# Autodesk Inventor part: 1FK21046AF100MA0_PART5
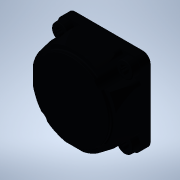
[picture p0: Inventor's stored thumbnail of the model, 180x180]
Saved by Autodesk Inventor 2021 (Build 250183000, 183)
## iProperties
Created: 2025-04
Part Number: 1FK21046AF100MA0_PART5
Material: Generic
Catalog Web Link: www.3dfindit.com
Description: -Servo synchronous motor
Document SubType Name: Modeling
Designer: psAdmin
Mass: 3.92604 g
Surface Area: 17.9521 cm^2
Volume: 3.92604 cm^3
Density: 1 g/cm^3
Appearance: PSOLRGB-48-56-69
Category: PARTsolutions
Title: 1FK21046AF100MA0_PART5
Author: Cadenas PARTsolutions
Comments: Servo synchronous motor
Sending System: PARTsolutions
Preprocessor: ST-DEVELOPER v19.3
PSOL_IDENT_0: {$CADENAS_DATA/23d-libs/siemens_ag/_cat_/4f/2b/1fk21046af100ma0.prj},213 {VTYP=3D},{NB=1FK21046AF100
PSOL_IDENT_1: MA0_PART5},{LINA=1FK21046AF100MA0_PART5},{NN=1FK21046AF100MA0_PART5},{NOPRJ=TRUE},{DATE=19.08.2025 1
PSOL_IDENT_2: 4:00:37},{GEOMDATE=30.07.2025 02:01:06},{VERSION=},{LINEID=10},{WBVAR=},{WBNUMERIC=}  {NB=1FK21046AF
PSOL_IDENT_3: 100MA0_PART5},{LINA=1FK21046AF100MA0_PART5},{KT=DUMMY},{PREVIEW=../../../_pool_/cb/72/p_d211_xx_0043
PSOL_IDENT_4: 4j.png},{DESCSHORT=SIMOTICS S-1FK2 HD, SINAMICS S210 3AC 400V-480V, 3.2 Nm, 3000 rpm},{DESCLONG=SIMO
PSOL_IDENT_5: TICS S-1FK2 HD servo motor M0=3.2 Nm; PN = 1 kW at nN=3000 rpm (380-480 V); PN = 0.5 kW at nN=1500 r
PSOL_IDENT_6: pm (200-240 V); with holding brake; degree of protection IP64; cylindrical shaft D19x40mm; absolute
PSOL_IDENT_7: encoder 22-bit + 12-bit multiturn (encoder AM22DQC); with OCC interface; plug size M17, rotatable; S
PSOL_IDENT_8: IMOTICS S-1FK2 servomotorfor a wide range of uses in industrial environments. SIMOTICS S‑1FK2 servom
PSOL_IDENT_9: otors are compact synchronous motors with a high dynamic performance that set themselves apart as a
PSOL_IDENT_10: result of their high power density, degree of protection and overload capability. The motors are ava
PSOL_IDENT_11: ilable in two variants: as High Dynamic variant (highest dynamic performance as a result of the low
PSOL_IDENT_12: intrinsic moment of inertia for applications demanding a high dynamic performance with low moved mas
PSOL_IDENT_13: ses) - and as Compact variant (precise and stable closed-loop control for medium up to large moved m
PSOL_IDENT_14: asses as a result of a medium intrinsic moment of inertia). SIMOTICSS‑1FK2 servomotors fully exploit
PSOL_IDENT_15: their strengths in a system with the SINAMICSS210 frequency converter and simple connection using t
PSOL_IDENT_16: he one cable connection (OCC). Advantages include the short control and positioning times, fast and
PSOL_IDENT_17: precise correction of disturbing quantities as well as stable control with a high dynamic performanc
PSOL_IDENT_18: e. The servo motors can be configured to address a wide range of requirements. For example with and
PSOL_IDENT_19: without holding brake, IP64 or IP65 degree of protection, singleturn or multiturn absolute encoders
PSOL_IDENT_20: - to name just a few. Further, the servomotors are available in different shaft heights extending fr
PSOL_IDENT_21: om 20 to 100. A shaft sealing ring is available to achieve an IP65 degree of protection and for subs
PSOL_IDENT_22: equent mounting at the motor or as spare part. SIMOTICS - the optimum motor for each and every motio
PSOL_IDENT_23: n control application.},{INTNO=195125049673},{SUPPLIERALTNO=1FK2104-6AF10-0MA0},{MANUID=1FK21046AF10
PSOL_IDENT_24: 0MA0},{MANUNAME=Siemens},{MANUTYPEDESC=Synchronous motor 1FK2-HD 3.2 NM},{AAU732=SIMOTICS},{AAO057=S
PSOL_IDENT_25: -1FK2},{AAU734=SIMOTICS S-1FK2 HD servo motor M0=3.2 Nm; PN = 1 kW at nN=3000 rpm (380-480 V); PN =
PSOL_IDENT_26: 0.5 kW at nN=1500 rpm (200-240 V); with holding brake; degree of protection IP64; cylindrical shaft
PSOL_IDENT_27: D19x40mm; absolute encoder 22-bit + 12-bit multiturn (encoder AM22DQC); with OCC interface; plug siz
PSOL_IDENT_28: e M17, rotatable;},{AAW338=Synchronous motor 1FK2-HD 3.2 NM},{AAO742=SIMOTICS},{AAO663=4042948694534
PSOL_IDENT_29: },{NOCUPEROU=1},{PRICEQUANTITY=1},{QUANTITYMIN=1},{QUANTITYINT=1},{CTN=85015220},{COO=DE},{AAO676=1F
PSOL_IDENT_30: K2104-6AF10-0MA0},{AAO677=Siemens AG},{ORDERUNIT=C62},{CONTENTUNIT=C62}
NB: 1FK21046AF100MA0_PART5
NT: Servo synchronous motor
NBSYN: $MANUID._PART5
LINA: 1FK21046AF100MA0_PART5
CATALOG: SIEMENS
PREVIEW: ../../../_pool_/cb/72/p_d211_xx_00434j.png
DESCSHORT: SIMOTICS S-1FK2 HD, SINAMICS S210 3AC 400V-480V, 3.2 Nm, 3000 rpm
DESCLONG: SIMOTICS S-1FK2 HD servo motor M0=3.2 Nm; PN = 1 kW at nN=3000 rpm (380-480 V); PN = 0.5 kW at nN=1500 rpm (200-240 V); with holding brake; degree of protection
INTNO: 195125049673
SUPPLIERALTNO: 1FK2104-6AF10-0MA0
MANUID: 1FK21046AF100MA0
MANUNAME: Siemens
MANUTYPEDESC: Synchronous motor 1FK2-HD 3.2 NM
AAU732: SIMOTICS
AAO057: S-1FK2
AAU734: SIMOTICS S-1FK2 HD servo motor M0=3.2 Nm; PN = 1 kW at nN=3000 rpm (380-480 V); PN = 0.5 kW at nN=1500 rpm (200-240 V); with holding brake; degree of protection
AAW338: Synchronous motor 1FK2-HD 3.2 NM
AAO742: SIMOTICS
AAO663: 4042948694534.0
NOCUPEROU: 1
PRICEQUANTITY: 1
QUANTITYMIN: 1
QUANTITYINT: 1
CTN: 85015220
COO: DE
ARTICLENO: 1FK21046AF100MA0_PART5
BOMINFO: 1FK21046AF100MA0_PART5
CREATOR: CADENAS GmbH
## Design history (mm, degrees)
feature "2025_04_17_14_59_39_0114"
body "Solid1"
